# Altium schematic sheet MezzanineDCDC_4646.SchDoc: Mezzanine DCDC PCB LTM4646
size Tabloid; Date: 9/7/2021; Engineer: J. Juneau; Organization: Altium Limited; Address1: L3, 12a Rodborough Rd; Address2: Frenchs Forest; Address3: NSW; Address4: Australia 2086; DocumentNumber: 1006; Revision: 1.2; SheetNumber: 2; SheetTotal: 4
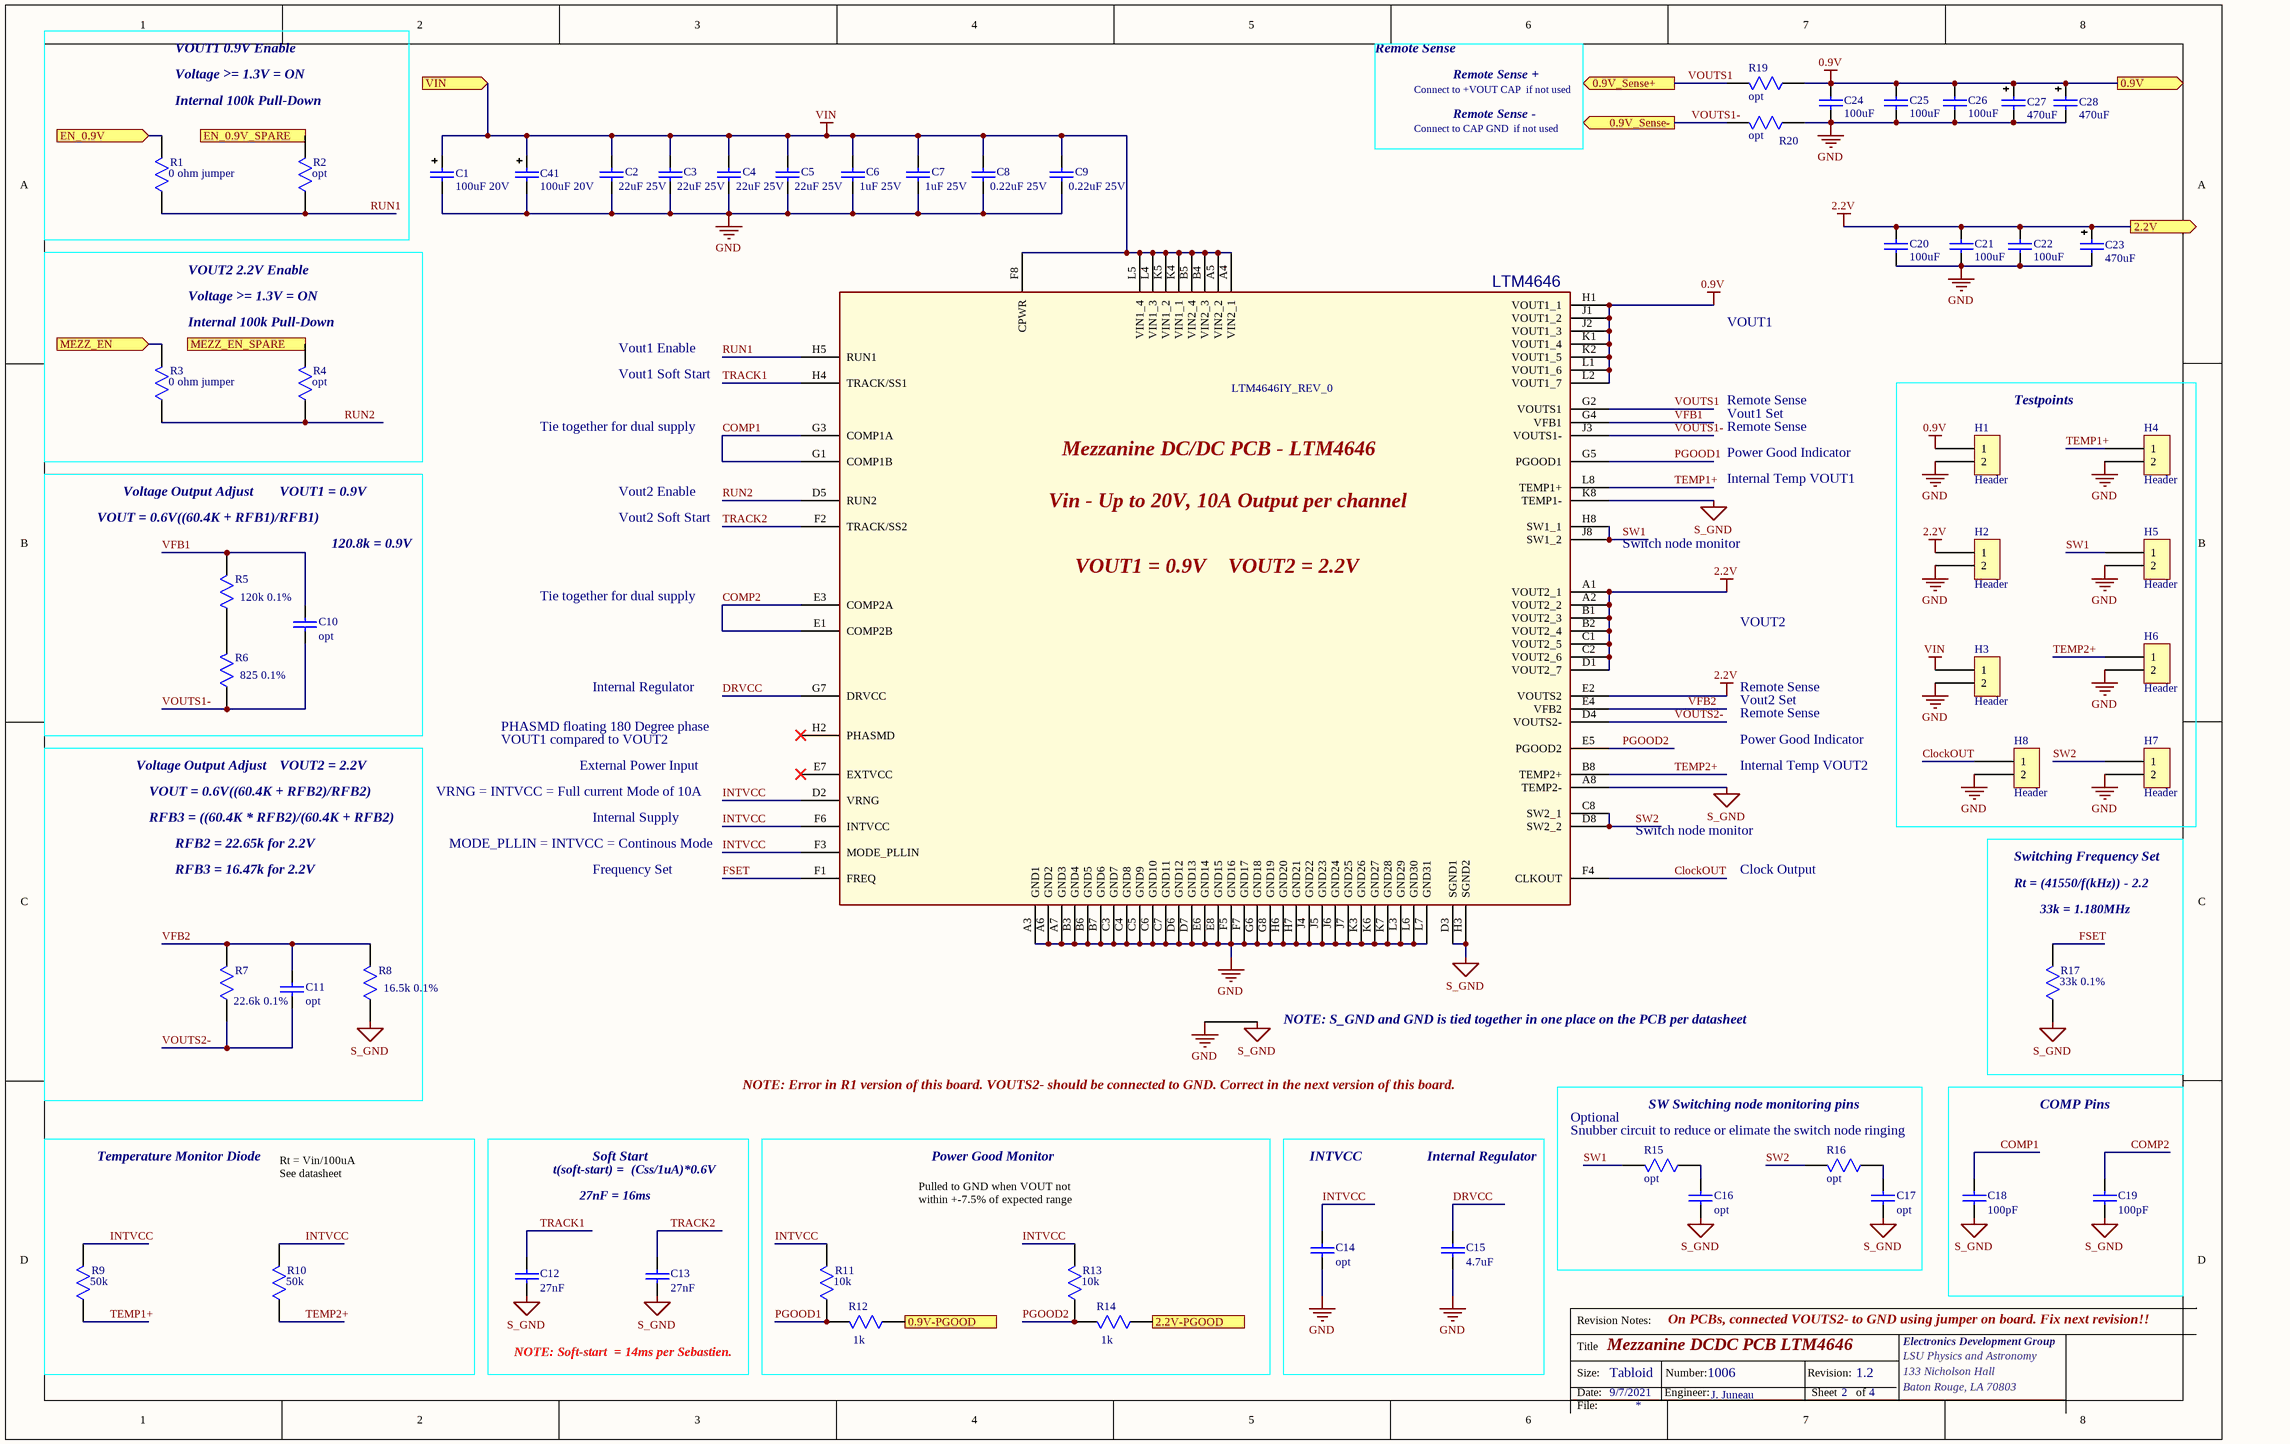
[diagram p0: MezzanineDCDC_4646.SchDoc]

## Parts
C1  value 100uF 20V  [CAP 2917 Tantalum Polarized TAJE107K020RNJ]  (hidden comment: TAJE107K020RNJ)
C2  value 22uF 25V  [CAP 1210 Murata]  (hidden comment: GRM32ER61E226KE15L)
C3  value 22uF 25V  [CAP 1210 Murata]  (hidden comment: GRM32ER61E226KE15L)
C4  value 22uF 25V  [CAP 1210 Murata]  (hidden comment: GRM32ER61E226KE15L)
C5  value 22uF 25V  [CAP 1210 Murata]  (hidden comment: GRM32ER61E226KE15L)
C6  value 1uF 25V  [Cap 0603 TDK]  (hidden comment: GCM188R71E105KA64D)
C7  value 1uF 25V  [Cap 0603 TDK]  (hidden comment: GCM188R71E105KA64D)
C8  value 0.22uF 25V  [Cap 0603 TDK]  (hidden comment: C1608X7R1E224K080AC)
C9  value 0.22uF 25V  [Cap 0603 TDK]  (hidden comment: C1608X7R1E224K080AC)
C10  opt  [Cap 0603 TDK]
C11  opt  [Cap 0603 TDK]
C12  value 27nF  [Cap 0603 TDK]  (hidden comment: 0603YC273KAT2A)
C13  value 27nF  [Cap 0603 TDK]  (hidden comment: 0603YC273KAT2A)
C14  value opt  [Cap 0603 TDK]  (hidden comment: C1608X5R1C475K080AC)
C15  value 4.7uF  [Cap 0603 TDK]  (hidden comment: C1608X5R1C475K080AC)
C16  opt  [Cap 0603 TDK]
C17  opt  [Cap 0603 TDK]
C18  value 100pF  [Cap 0603 TDK]  (hidden comment: 0603YC101KAT2A)
C19  value 100pF  [Cap 0603 TDK]  (hidden comment: 0603YC101KAT2A)
C20  value 100uF  [CAP 1210 Murata]  (hidden comment: GRM32ER60J107ME20K)
C21  value 100uF  [CAP 1210 Murata]  (hidden comment: GRM32ER60J107ME20K)
C22  value 100uF  [CAP 1210 Murata]  (hidden comment: GRM32ER60J107ME20K)
C23  value 470uF  [CAP 2917 Tantalum Polarized]  (hidden comment: 4TPE470MCL)
C24  value 100uF  [CAP 1210 Murata]  (hidden comment: GRM32ER60J107ME20K)
C25  value 100uF  [CAP 1210 Murata]  (hidden comment: GRM32ER60J107ME20K)
C26  value 100uF  [CAP 1210 Murata]  (hidden comment: GRM32ER60J107ME20K)
C27  value 470uF  [CAP 2917 Tantalum Polarized]  (hidden comment: 4TPE470MCL)
C28  value 470uF  [CAP 2917 Tantalum Polarized]  (hidden comment: 4TPE470MCL)
C41  value 100uF 20V  [CAP 2917 Tantalum Polarized TAJE107K020RNJ]  (hidden comment: TAJE107K020RNJ)
H1  Header  [Header 2Pin]
H2  Header  [Header 2Pin]
H3  Header  [Header 2Pin]
H4  Header  [Header 2Pin]
H5  Header  [Header 2Pin]
H6  Header  [Header 2Pin]
H7  Header  [Header 2Pin]
H8  Header  [Header 2Pin]
R1  value 0 ohm jumper  [Resistor ERJ2G/CRCW 0402]  (hidden comment: CRCW04020000ZSTD)
R2  opt  [Resistor ERJ2G/CRCW 0402]
R3  value 0 ohm jumper  [Resistor ERJ2G/CRCW 0402]  (hidden comment: CRCW04020000ZSTD)
R4  opt  [Resistor ERJ2G/CRCW 0402]
R5  value 120k 0.1%  [Resistor 0603 - ERJ]  (hidden comment: ERA-3AEB124V)
R6  value 825 0.1%  [Resistor 0603 - ERJ]  (hidden comment: ERA-3AEB8250V)
R7  value 22.6k 0.1%  [Resistor 0603 - ERJ]  (hidden comment: ERA-3AEB2262V)
R8  value 16.5k 0.1%  [Resistor 0603 - ERJ]  (hidden comment: ERA-3AEB1652V)
R9  value 50k  [Resistor ERJ2G/CRCW 0402]  (hidden comment: ERA-2AEB4992X)
R10  value 50k  [Resistor ERJ2G/CRCW 0402]  (hidden comment: ERA-2AEB4992X)
R11  value 10k  [Resistor ERJ2G/CRCW 0402]  (hidden comment: ERJ-2GEJ103X)
R12  value 1k  [Resistor ERJ2G/CRCW 0402]  (hidden comment: ERJ-2GEJ102X)
R13  value 10k  [Resistor ERJ2G/CRCW 0402]  (hidden comment: ERJ-2GEJ103X)
R14  value 1k  [Resistor ERJ2G/CRCW 0402]  (hidden comment: ERJ-2GEJ102X)
R15  opt  [Resistor ERJ2G/CRCW 0402]
R16  opt  [Resistor ERJ2G/CRCW 0402]
R17  value 33k 0.1%  [Resistor 0603 - ERJ]  (hidden comment: ERA-3AEB333V)
R19  opt  [Resistor ERJ2G/CRCW 0402]
R20  opt  [Resistor ERJ2G/CRCW 0402]
U1  LTM4646IY_REV_0  [LTM4646]  (net tie, no BOM)

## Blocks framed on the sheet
Testpoints: H1-H8
Switching Frequency Set: R17
COMP Pins: C18 C19
Temperature Monitor Diode: R9 R10
Soft Start: C12 C13
Power Good Monitor: R11-R14

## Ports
0.9V (out), 0.9V-PGOOD (out), 0.9V_Sense+ (out), 0.9V_Sense- (out), 2.2V (out), 2.2V-PGOOD (out), EN_0.9V (in), EN_0.9V_SPARE (in), MEZZ_EN (in), MEZZ_EN_SPARE (in), VIN (in)

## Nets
0.9V: C24.1 C25.1 C26.1 C27.1 C28.1 H1.1 R19.1 U1.H1(VOUT1_1) U1.J1(VOUT1_2) U1.J2(VOUT1_3) U1.K1(VOUT1_4) U1.K2(VOUT1_5) U1.L1(VOUT1_6) U1.L2(VOUT1_7) ; port 0.9V
2.2V: C20.1 C21.1 C22.1 C23.1 H2.1 U1.A1(VOUT2_1) U1.A2(VOUT2_2) U1.B1(VOUT2_3) U1.B2(VOUT2_4) U1.C1(VOUT2_5) U1.C2(VOUT2_6) U1.D1(VOUT2_7) U1.E2(VOUTS2) ; port 2.2V
GND: C1.2 C2.2 C3.2 C4.2 C5.2 C6.2 C7.2 C8.2 C9.2 C14.2 C15.2 C20.2 C21.2 C22.2 C23.2 C24.2 C25.2 C26.2 C27.2 C28.2 C41.2 H1.2 H2.2 H3.2 H4.2 H5.2 H6.2 H7.2 H8.2 R20.1 U1.A3(GND1) U1.A6(GND2) U1.A7(GND3) U1.B3(GND4) U1.B6(GND5) U1.B7(GND6) U1.C3(GND7) U1.C4(GND8) U1.C5(GND9) U1.C6(GND10) U1.C7(GND11) U1.D6(GND12) U1.D7(GND13) U1.E6(GND14) U1.E8(GND15) U1.F5(GND16) U1.F7(GND17) U1.G6(GND18) U1.G8(GND19) U1.H6(GND20) U1.H7(GND21) U1.J4(GND22) U1.J5(GND23) U1.J6(GND24) U1.J7(GND25) U1.K3(GND26) U1.K6(GND27) U1.K7(GND28) U1.L3(GND29) U1.L6(GND30) U1.L7(GND31)
S_GND: C12.2 C13.2 C16.2 C17.2 C18.2 C19.2 R8.1 R17.1 U1.A8(TEMP2-) U1.D3(SGND1) U1.H3(SGND2) U1.K8(TEMP1-)
VIN: C1.1 C2.1 C3.1 C4.1 C5.1 C6.1 C7.1 C8.1 C9.1 C41.1 H3.1 U1.A4(VIN2_1) U1.A5(VIN2_2) U1.B4(VIN2_3) U1.B5(VIN2_4) U1.F8(CPWR) U1.K4(VIN1_1) U1.K5(VIN1_2) U1.L4(VIN1_3) U1.L5(VIN1_4) ; port VIN
0.9V-PGOOD: R12.1 ; port 0.9V-PGOOD
2.2V-PGOOD: R14.1 ; port 2.2V-PGOOD
ClockOUT: H8.1 U1.F4(CLKOUT)
COMP1: C18.1 U1.G1(COMP1B) U1.G3(COMP1A)
COMP2: C19.1 U1.E1(COMP2B) U1.E3(COMP2A)
DRVCC: C15.1 U1.G7(DRVCC)
EN_0.9V: R1.2 ; port EN_0.9V
EN_0.9V_SPARE: R2.2 ; port EN_0.9V_SPARE
FSET: R17.2 U1.F1(FREQ)
INTVCC: C14.1 R9.2 R10.2 R11.2 R13.2 U1.D2(VRNG) U1.F3(MODE_PLLIN) U1.F6(INTVCC)
MEZZ_EN: R3.2 ; port MEZZ_EN
MEZZ_EN_SPARE: R4.2 ; port MEZZ_EN_SPARE
PGOOD1: R11.1 R12.2 U1.G5(PGOOD1)
PGOOD2: R13.1 R14.2 U1.E5(PGOOD2)
RUN1: R1.1 R2.1 U1.H5(RUN1)
RUN2: R3.1 R4.1 U1.D5(RUN2)
SW1: H5.1 R15.2 U1.H8(SW1_1) U1.J8(SW1_2)
SW2: H7.1 R16.2 U1.C8(SW2_1) U1.D8(SW2_2)
TEMP1+: H4.1 R9.1 U1.L8(TEMP1+)
TEMP2+: H6.1 R10.1 U1.B8(TEMP2+)
TRACK1: C12.1 U1.H4(TRACK/SS1)
TRACK2: C13.1 U1.F2(TRACK/SS2)
VFB1: C10.1 R5.2 U1.G4(VFB1)
VFB2: C11.1 R7.2 R8.2 U1.E4(VFB2)
VOUTS1: R19.2 U1.G2(VOUTS1) ; port 0.9V_Sense+
VOUTS1-: C10.2 R6.1 R20.2 U1.J3(VOUTS1-) ; port 0.9V_Sense-
VOUTS2-: C11.2 R7.1 U1.D4(VOUTS2-)
NetC16_1: C16.1 R15.1
NetC17_1: C17.1 R16.1
NetR5_1: R5.1 R6.2

Not connected (* = marked no-connect by the designer): U1 E7(EXTVCC)* H2(PHASMD)*

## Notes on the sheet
- VOUT1 0.9V Enable
- Voltage >= 1.3V = ON
- Remote Sense
- Connect to +VOUT CAP  if not used
- Remote Sense +
- Internal 100k Pull-Down
- Connect to CAP GND  if not used
- Remote Sense -
- VOUT2 2.2V Enable
- Vout1 Enable
- VOUT1
- Vout1 Soft Start
- Vout1 Set
- Tie together for dual supply
- (near U1) Mezzanine DC/DC PCB - LTM4646
- Internal Temp VOUT1
- Power Good Indicator
- (near R5) VOUT = 0.6V((60.4K + RFB1)/RFB1)
- Voltage Output Adjust
- VOUT1 = 0.9V
- 120.8k = 0.9V
- Vout2 Enable
- Vout2 Soft Start
- (near U1) Vin - Up to 20V, 10A Output per channel
- Switch node monitor
- (near U1) VOUT1 = 0.9V    VOUT2 = 2.2V
- VOUT2
- PHASMD floating 180 Degree phase
- VOUT1 compared to VOUT2
- Internal Regulator
- Vout2 Set
- VOUT = 0.6V((60.4K + RFB2)/RFB2)
- VOUT2 = 2.2V
- VRNG = INTVCC = Full current Mode of 10A
- External Power Input
- Internal Temp VOUT2
- RFB3 = ((60.4K * RFB2)/(60.4K + RFB2)
- RFB2 = 22.65k for 2.2V
- RFB3 = 16.47k for 2.2V
- MODE_PLLIN = INTVCC = Continous Mode
- Internal Supply
- Frequency Set
- Clock Output
- Rt = (41550/f(kHz)) - 2.2
- (near R17) 33k = 1.180MHz
- NOTE: S_GND and GND is tied together in one place on the PCB per datasheet
- NOTE: Error in R1 version of this board. VOUTS2- should be connected to GND. Correct in the next version of this board.
- Snubber circuit to reduce or elimate the switch node ringing
- (near R15) Optional
- SW Switching node monitoring pins
- Rt = Vin/100uA
  See datasheet
- t(soft-start) =  (Css/1uA)*0.6V
- 27nF = 16ms
- Pulled to GND when VOUT not within +-7.5% of expected range
- INTVCC
- On PCBs, connected VOUTS2- to GND using jumper on board. Fix next revision!!
- NOTE: Soft-start  = 14ms per Sebastien.
- Labels drawn without touching a wire or pin: GND, S_GND

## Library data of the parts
C1 C41 = Capacitor 2917 TAJE107K020RNJ: 100µF Molded Tantalum Capacitors 20V 2917 (7343 Metric) 400mOhm
C2-C5 = Capacitor 1210: 22µF ±10% 25V Ceramic Capacitor X5R 1210 (3225 Metric)
C6 C7 = Capacitor 0603 TDK: 1µF ±10% 25V Ceramic Capacitor X7R 0603 (1608 Metric)
C8 C9 = Capacitor 0603 TDK: CAP CER 0.22UF 25V X7R 0603
C10 C11 C16 C17 = Capacitor 0603 TDK: Capacitor 0603
C12 C13 = Capacitor 0603 TDK: 0.027µF ±10% 16V Ceramic Capacitor X7R 0603 (1608 Metric) /
C14 C15 = Capacitor 0603 TDK: CAP CER 4.7UF 16V X5R 0603
C18 C19 = Capacitor 0603 TDK: 100pF ±10% 16V Ceramic Capacitor X7R 0603 (1608 Metric) /
C20-C22 C24-C26 = Capacitor 1210: 100µF ±20% 6.3V Ceramic Capacitor X5R 1210 (3225 Metric)
C23 C27 C28 = Capacitor 2917 Panasonic: 470µF Molded Tantalum Polymer Capacitor 4V 2917 (7343 Metric) 12mOhm @ 100kHz
H1-H8 = Header - 2Pin: Connector Header Through Hole 2 position 0.100" (2.54mm)
R1 R3 = ERJ2G Resistor 0402: Jumper 0.063W, 1/16W Chip Resistor 0402 (1005 Metric) Automotive AEC-Q200 Thick Film
R2 R4 R15 R16 R19 R20 = ERJ2G Resistor 0402: Resistor 0402
R5 = Resistor 0603: 120 kOhms ±0.1% 0.1W, 1/10W Chip Resistor 0603 (1608 Metric) Automotive AEC-Q200 Thin Film
R6 = Resistor 0603: RES SMD 825 OHM 0.1% 1/10W 0603
R7 = Resistor 0603: 22.6 kOhms ±0.1% 0.1W, 1/10W Chip Resistor 0603 (1608 Metric) Automotive AEC-Q200 Thin Film
R8 = Resistor 0603: 16.5 kOhms ±0.1% 0.1W, 1/10W Chip Resistor 0603 (1608 Metric) Automotive AEC-Q200 Thin Film
R9 R10 = ERJ2G Resistor 0402: 49.9 ±0.1% 0.063W, 1/16W Chip Resistor 0402 (1005 Metric) Automotive AEC-Q200 Thin Film
R11 R13 = ERJ2G Resistor 0402: RES SMD 10K OHM 5% 1/10W 0402
R12 R14 = ERJ2G Resistor 0402: RES SMD 1K OHM 5% 1/10W 0402
R17 = Resistor 0603: 33 ±0.1% 0.1W, 1/10W Chip Resistor 0603 (1608 Metric) Automotive AEC-Q200 Thin Film
U1 = LTM4646IY 05-11-0399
